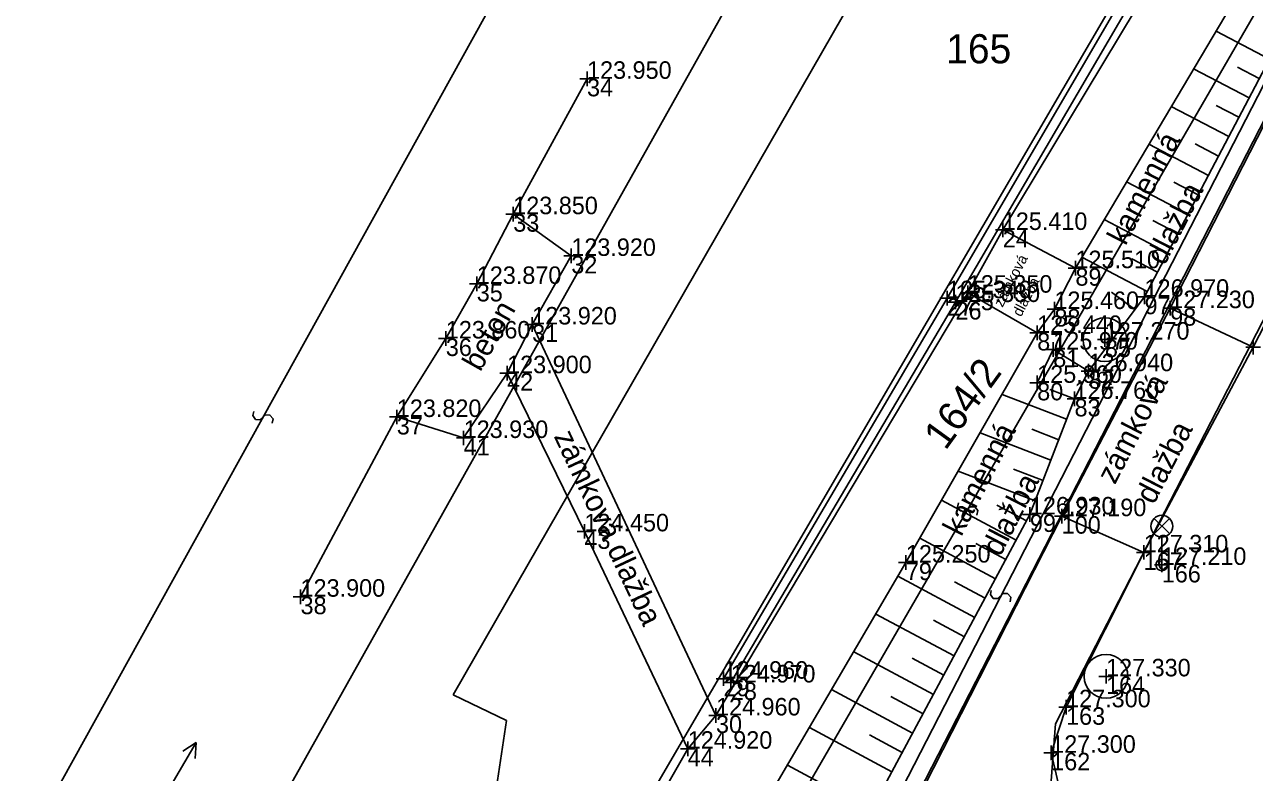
# Model space of a CAD drawing. Extents: x -747268 to -747054, y -964730 to -964532.
# Drawn here: x -747222.18 to -747180.02, y -964632.88 to -964607.25 of the extents above; entities that cross this region are included whole.
import ezdxf

# ---------------------------------------------------------------- set-up
doc = ezdxf.new("R2010")
doc.units = 0
for name, color, linetype in [('Body polohopisu', 7, 'Continuous'), ('Doplňkové značky', 7, 'Continuous'), ('KM', 7, 'Continuous'), ('Ploty_opěrné zdi', 7, 'Continuous'), ('Popisy objektů_povrchů', 7, 'Continuous'), ('Rozhraní ploch', 7, 'Continuous'), ('Vnitřní kresba', 7, 'Continuous'), ('Výškopis', 7, 'Continuous'), ('Výšky bodů', 7, 'Continuous'), ('Čísla bodů', 7, 'Continuous')]:
    doc.layers.add(name, color=color, linetype=linetype)

msp = doc.modelspace()

# ---------------------------------------------------------------- linework, layer by layer
at = {"layer": 'Body polohopisu'}
for p, q in [((-747202.9, -964609.11), (-747203.15, -964609.11)), ((-747202.9, -964609.11), (-747202.9, -964608.86)), ((-747202.9, -964609.11), (-747202.65, -964609.11)), ((-747202.9, -964609.11), (-747202.9, -964609.36)), ((-747205.43, -964613.75), (-747205.68, -964613.75)), ((-747205.43, -964613.75), (-747205.43, -964613.5)), ((-747205.43, -964613.75), (-747205.18, -964613.75)), ((-747205.43, -964613.75), (-747205.43, -964614)), ((-747188.65, -964614.29), (-747188.65, -964614.04)), ((-747188.65, -964614.29), (-747188.9, -964614.29)), ((-747188.65, -964614.29), (-747188.4, -964614.29)), ((-747188.65, -964614.29), (-747188.65, -964614.54)), ((-747203.44, -964615.18), (-747203.44, -964614.93)), ((-747203.44, -964615.18), (-747203.69, -964615.18)), ((-747203.44, -964615.18), (-747203.19, -964615.18)), ((-747203.44, -964615.18), (-747203.44, -964615.43)), ((-747186.16, -964615.6), (-747186.16, -964615.35)), ((-747206.68, -964616.14), (-747206.68, -964615.89)), ((-747186.16, -964615.6), (-747186.41, -964615.6)), ((-747186.16, -964615.6), (-747185.91, -964615.6)), ((-747186.16, -964615.6), (-747186.16, -964615.85)), ((-747206.68, -964616.14), (-747206.93, -964616.14)), ((-747206.68, -964616.14), (-747206.43, -964616.14)), ((-747206.68, -964616.14), (-747206.68, -964616.39)), ((-747189.85, -964616.44), (-747189.85, -964616.19)), ((-747190.56, -964616.63), (-747190.81, -964616.63)), ((-747190.56, -964616.63), (-747190.56, -964616.38)), ((-747190.56, -964616.63), (-747190.31, -964616.63)), ((-747190.56, -964616.63), (-747190.56, -964616.88)), ((-747190.27, -964616.76), (-747190.27, -964616.51)), ((-747189.85, -964616.44), (-747190.1, -964616.44)), ((-747189.85, -964616.44), (-747189.6, -964616.44)), ((-747189.85, -964616.44), (-747189.85, -964616.69)), ((-747183.79, -964616.58), (-747184.04, -964616.58)), ((-747183.79, -964616.58), (-747183.79, -964616.33)), ((-747183.79, -964616.58), (-747183.54, -964616.58)), ((-747183.79, -964616.58), (-747183.79, -964616.83)), ((-747182.91, -964616.97), (-747182.91, -964616.72)), ((-747190.27, -964616.76), (-747190.52, -964616.76)), ((-747190.27, -964616.76), (-747190.02, -964616.76)), ((-747190.27, -964616.76), (-747190.27, -964617.01)), ((-747186.88, -964617), (-747187.13, -964617)), ((-747186.88, -964617), (-747186.88, -964616.75)), ((-747186.88, -964617), (-747186.63, -964617)), ((-747186.88, -964617), (-747186.88, -964617.25)), ((-747182.91, -964616.97), (-747183.16, -964616.97)), ((-747182.91, -964616.97), (-747182.66, -964616.97)), ((-747182.91, -964616.97), (-747182.91, -964617.22)), ((-747204.78, -964617.53), (-747205.03, -964617.53)), ((-747204.78, -964617.53), (-747204.78, -964617.28)), ((-747204.78, -964617.53), (-747204.53, -964617.53)), ((-747204.78, -964617.53), (-747204.78, -964617.78)), ((-747187.47, -964617.82), (-747187.47, -964617.57)), ((-747207.74, -964618.01), (-747207.74, -964617.76)), ((-747187.47, -964617.82), (-747187.72, -964617.82)), ((-747187.47, -964617.82), (-747187.22, -964617.82)), ((-747187.47, -964617.82), (-747187.47, -964618.07)), ((-747185.15, -964618.05), (-747185.15, -964617.8)), ((-747207.74, -964618.01), (-747207.99, -964618.01)), ((-747207.74, -964618.01), (-747207.49, -964618.01)), ((-747207.74, -964618.01), (-747207.74, -964618.26)), ((-747186.92, -964618.39), (-747187.17, -964618.39)), ((-747186.92, -964618.39), (-747186.92, -964618.14)), ((-747186.92, -964618.39), (-747186.67, -964618.39)), ((-747186.92, -964618.39), (-747186.92, -964618.64)), ((-747185.15, -964618.05), (-747185.4, -964618.05)), ((-747185.15, -964618.05), (-747184.9, -964618.05)), ((-747185.15, -964618.05), (-747185.15, -964618.3)), ((-747180.07, -964618.31), (-747180.32, -964618.31)), ((-747180.07, -964618.31), (-747180.07, -964618.06)), ((-747180.07, -964618.31), (-747179.82, -964618.31)), ((-747180.07, -964618.31), (-747180.07, -964618.56)), ((-747205.64, -964619.2), (-747205.89, -964619.2)), ((-747205.64, -964619.2), (-747205.64, -964618.95)), ((-747205.64, -964619.2), (-747205.39, -964619.2)), ((-747205.64, -964619.2), (-747205.64, -964619.45)), ((-747185.71, -964619.13), (-747185.96, -964619.13)), ((-747185.71, -964619.13), (-747185.71, -964618.88)), ((-747185.71, -964619.13), (-747185.46, -964619.13)), ((-747185.71, -964619.13), (-747185.71, -964619.38)), ((-747187.47, -964619.53), (-747187.72, -964619.53)), ((-747187.47, -964619.53), (-747187.47, -964619.28)), ((-747187.47, -964619.53), (-747187.22, -964619.53)), ((-747187.47, -964619.53), (-747187.47, -964619.78)), ((-747186.19, -964620.08), (-747186.44, -964620.08)), ((-747186.19, -964620.08), (-747186.19, -964619.83)), ((-747186.19, -964620.08), (-747185.94, -964620.08)), ((-747186.19, -964620.08), (-747186.19, -964620.33)), ((-747209.42, -964620.7), (-747209.42, -964620.45)), ((-747209.42, -964620.7), (-747209.67, -964620.7)), ((-747209.42, -964620.7), (-747209.17, -964620.7)), ((-747209.42, -964620.7), (-747209.42, -964620.95)), ((-747207.13, -964621.42), (-747207.13, -964621.17)), ((-747207.13, -964621.42), (-747207.38, -964621.42)), ((-747207.13, -964621.42), (-747206.88, -964621.42)), ((-747207.13, -964621.42), (-747207.13, -964621.67)), ((-747187.72, -964624.04), (-747187.72, -964623.79)), ((-747186.63, -964624.1), (-747186.63, -964623.85)), ((-747187.72, -964624.04), (-747187.97, -964624.04)), ((-747187.72, -964624.04), (-747187.47, -964624.04)), ((-747187.72, -964624.04), (-747187.72, -964624.29)), ((-747186.63, -964624.1), (-747186.88, -964624.1)), ((-747186.63, -964624.1), (-747186.38, -964624.1)), ((-747186.63, -964624.1), (-747186.63, -964624.35)), ((-747202.99, -964624.62), (-747203.24, -964624.62)), ((-747202.99, -964624.62), (-747202.99, -964624.37)), ((-747202.99, -964624.62), (-747202.74, -964624.62)), ((-747202.99, -964624.62), (-747202.99, -964624.87)), ((-747183.82, -964625.34), (-747183.82, -964625.09)), ((-747191.97, -964625.69), (-747191.97, -964625.44)), ((-747183.82, -964625.34), (-747184.07, -964625.34)), ((-747183.82, -964625.34), (-747183.57, -964625.34)), ((-747183.82, -964625.34), (-747183.82, -964625.59)), ((-747183.2, -964625.77), (-747183.2, -964625.52)), ((-747191.97, -964625.69), (-747192.22, -964625.69)), ((-747191.97, -964625.69), (-747191.72, -964625.69)), ((-747191.97, -964625.69), (-747191.97, -964625.94)), ((-747183.2, -964625.77), (-747183.45, -964625.77)), ((-747183.2, -964625.77), (-747182.95, -964625.77)), ((-747183.2, -964625.77), (-747183.2, -964626.02)), ((-747212.72, -964626.86), (-747212.72, -964626.61)), ((-747212.72, -964626.86), (-747212.97, -964626.86)), ((-747212.72, -964626.86), (-747212.47, -964626.86)), ((-747212.72, -964626.86), (-747212.72, -964627.11)), ((-747185.11, -964629.59), (-747185.11, -964629.34)), ((-747198.22, -964629.67), (-747198.47, -964629.67)), ((-747198.22, -964629.67), (-747198.22, -964629.42)), ((-747198.22, -964629.67), (-747197.97, -964629.67)), ((-747198.22, -964629.67), (-747198.22, -964629.92)), ((-747197.97, -964629.8), (-747198.22, -964629.8)), ((-747197.97, -964629.8), (-747197.97, -964629.55)), ((-747197.97, -964629.8), (-747197.72, -964629.8)), ((-747197.97, -964629.8), (-747197.97, -964630.05)), ((-747185.11, -964629.59), (-747185.36, -964629.59)), ((-747185.11, -964629.59), (-747184.86, -964629.59)), ((-747185.11, -964629.59), (-747185.11, -964629.84)), ((-747186.48, -964630.65), (-747186.73, -964630.65)), ((-747186.48, -964630.65), (-747186.48, -964630.4)), ((-747186.48, -964630.65), (-747186.23, -964630.65)), ((-747186.48, -964630.65), (-747186.48, -964630.9)), ((-747198.48, -964630.93), (-747198.73, -964630.93)), ((-747198.48, -964630.93), (-747198.48, -964630.68)), ((-747198.48, -964630.93), (-747198.23, -964630.93)), ((-747198.48, -964630.93), (-747198.48, -964631.18)), ((-747199.45, -964632.07), (-747199.45, -964631.82)), ((-747199.45, -964632.07), (-747199.7, -964632.07)), ((-747199.45, -964632.07), (-747199.2, -964632.07)), ((-747199.45, -964632.07), (-747199.45, -964632.32)), ((-747186.99, -964632.21), (-747187.24, -964632.21)), ((-747186.99, -964632.21), (-747186.99, -964631.96)), ((-747186.99, -964632.21), (-747186.74, -964632.21)), ((-747186.99, -964632.21), (-747186.99, -964632.46))]:
    msp.add_line(p, q, dxfattribs=at)
at = {"layer": 'Doplňkové značky'}
for p, q in [((-747183.464, -964624.708), (-747182.936, -964624.18)), ((-747182.928, -964624.705), (-747183.456, -964624.176)), ((-747183.2, -964624.82), (-747183.2, -964625.57))]:
    msp.add_line(p, q, dxfattribs=at)
for centre, radius in [((-747185.15, -964618.05), 0.75), ((-747183.2, -964624.445), 0.375), ((-747183.2, -964625.77), 0.2), ((-747185.11, -964629.59), 0.75)]:
    msp.add_circle(centre, radius, dxfattribs=at)
at = {"layer": 'KM'}
for p, q in [((-747217.82, -964634.444), (-747216.296, -964631.86)), ((-747216.296, -964631.86), (-747216.76, -964632.153)), ((-747216.296, -964631.86), (-747216.329, -964632.408))]:
    msp.add_line(p, q, dxfattribs=at)
for points in [[(-747258.428, -964718.402), (-747225.89, -964656.18), (-747178.58, -964571.79), (-747161.768, -964542.826)], [(-747245.973, -964725.574), (-747237.39, -964710.13), (-747213.15, -964663.66), (-747212.04, -964661.58), (-747205.52, -964649.38), (-747207.93, -964646.01), (-747172.64, -964585.56), (-747171.18, -964583.16), (-747172.38, -964582.51), (-747172.75, -964582.31), (-747169.52, -964576.73), (-747168.08, -964577.53), (-747165.21, -964574.13), (-747160.86, -964564.14), (-747155.16, -964551.47), (-747155.48, -964551.37), (-747155.09, -964550.12), (-747154.28, -964550.33), (-747154.06, -964549.5), (-747153.365, -964547.044)], [(-747242.047, -964727.609), (-747230.16, -964705.36), (-747208.97, -964665.66), (-747208.88, -964665.32), (-747209.05, -964664.92), (-747208.39, -964663.57), (-747207.91, -964663.49), (-747207.6, -964663.09), (-747199.41, -964647.48), (-747199.14, -964646.95), (-747194.94, -964639.04), (-747194.8, -964638.66), (-747194.08, -964638.4), (-747193.89, -964638.17), (-747178.12, -964607.48), (-747165.52, -964582.92), (-747162.81, -964577.62), (-747161.38, -964574.2), (-747160.49, -964571.42), (-747153.77, -964550.39), (-747154.12, -964550.42), (-747153.81, -964549.44), (-747153.109, -964547.254)], [(-747149.729, -964549.086), (-747149.93, -964549.71), (-747150.35, -964549.8), (-747157.75, -964573.23), (-747158.53, -964575.6), (-747159.7, -964578.37), (-747163.23, -964585.33), (-747175.42, -964609.03), (-747186.84, -964631.22), (-747187.01, -964633.47), (-747185.08, -964635.94), (-747196.29, -964656.98), (-747198.54, -964658.68), (-747199.84, -964658.63), (-747201.84, -964659.38), (-747202.78, -964660.64), (-747203.73, -964662.42), (-747219.36, -964691.72)]]:
    msp.add_lwpolyline(points, dxfattribs=at)
at = {"layer": 'Ploty_opěrné zdi'}
for points in [[(-747169.11, -964579.94), (-747175.36, -964590.58), (-747182.97, -964603.61), (-747190.56, -964616.63), (-747198.22, -964629.67)], [(-747168.99, -964580.15), (-747175.05, -964590.69), (-747182.64, -964603.71), (-747190.27, -964616.76), (-747197.97, -964629.8)], [(-747187.47, -964619.53), (-747186.92, -964618.39), (-747185.71, -964619.13), (-747186.19, -964620.08)]]:
    msp.add_lwpolyline(points, dxfattribs=at)
at = {"layer": 'Rozhraní ploch'}
for points in [[(-747154.77, -964553.45), (-747158.98, -964567.07), (-747160.49, -964571.42), (-747165.45, -964575.44), (-747168.74, -964580.34), (-747174.87, -964590.85), (-747182.36, -964603.84), (-747188.65, -964614.29), (-747189.85, -964616.44), (-747198.48, -964630.93), (-747204.78, -964617.53), (-747203.44, -964615.18), (-747205.43, -964613.75), (-747206.68, -964616.14)], [(-747164.8, -964581.46), (-747168.98, -964589.75), (-747182.91, -964616.97), (-747186.63, -964624.1), (-747193.85, -964638.28), (-747194.38, -964638.56), (-747199.08, -964647.44), (-747204.82, -964658.33), (-747208.77, -964665.45), (-747214.7, -964676.73), (-747220.35, -964687.31), (-747228.95, -964703.36)], [(-747186.16, -964615.6), (-747180.42, -964605.92), (-747172.31, -964591.8), (-747166.51, -964582.26), (-747165.78, -964581.39), (-747164.8, -964581.46)], [(-747185.39, -964635.93), (-747186.36, -964634.9), (-747186.99, -964632.21), (-747186.48, -964630.65), (-747183.82, -964625.34), (-747180.07, -964618.31), (-747170.65, -964599.99), (-747161.67, -964582.51), (-747155.9, -964583.06)], [(-747188.65, -964614.29), (-747186.16, -964615.6)], [(-747186.88, -964617), (-747186.16, -964615.6)], [(-747206.68, -964616.14), (-747207.74, -964618.01)], [(-747187.47, -964617.82), (-747189.85, -964616.44)], [(-747211.81, -964661.77), (-747212.46, -964661), (-747212.25, -964659.9), (-747208, -964652.82), (-747198.3, -964636.51), (-747191.97, -964625.69), (-747187.47, -964617.82), (-747186.88, -964617)], [(-747180.07, -964618.31), (-747182.91, -964616.97)], [(-747205.64, -964619.2), (-747204.78, -964617.53)], [(-747207.74, -964618.01), (-747209.42, -964620.7), (-747207.13, -964621.42), (-747205.64, -964619.2), (-747202.99, -964624.62), (-747199.45, -964632.07), (-747215.93, -964660.89), (-747224.57, -964675.08), (-747231.76, -964687.56), (-747236.28, -964694.89), (-747237.94, -964696.27), (-747242.26, -964695.59), (-747246.85, -964693), (-747247.82, -964691.84), (-747248.23, -964692.9)], [(-747186.63, -964624.1), (-747183.82, -964625.34)], [(-747199.45, -964632.07), (-747198.48, -964630.93)]]:
    msp.add_lwpolyline(points, dxfattribs=at)
at = {"layer": 'Vnitřní kresba'}
for p, q in [((-747231.87, -964652.97), (-747184.5, -964567.43)), ((-747179.63, -964581.7), (-747207.49, -964630.22)), ((-747199.15, -964639.91), (-747166.09, -964582.82)), ((-747166.09, -964582.82), (-747194.8, -964638.66)), ((-747207.49, -964630.22), (-747205.66, -964631.1)), ((-747205.66, -964631.1), (-747207.93, -964646.01))]:
    msp.add_line(p, q, dxfattribs=at)
for points in [[(-747213.69, -964620.916), (-747213.661, -964620.76), (-747213.768, -964620.633), (-747213.92, -964620.628), (-747214.11, -964620.797), (-747214.262, -964620.782), (-747214.355, -964620.65), (-747214.322, -964620.508)], [(-747189.541, -964624.066), (-747189.509, -964623.911), (-747189.613, -964623.781), (-747189.765, -964623.774), (-747189.959, -964623.939), (-747190.11, -964623.921), (-747190.201, -964623.788), (-747190.165, -964623.646)], [(-747188.4, -964627.032), (-747188.376, -964626.875), (-747188.486, -964626.751), (-747188.638, -964626.752), (-747188.824, -964626.926), (-747188.976, -964626.916), (-747189.073, -964626.787), (-747189.044, -964626.644)]]:
    msp.add_lwpolyline(points, dxfattribs=at)
at = {"layer": 'Výškopis'}
for points in [[(-747164.8, -964581.46), (-747168.98, -964589.75), (-747173.09, -964596.22), (-747183.79, -964616.58), (-747185.71, -964619.13)], [(-747179.51, -964608.436), (-747181.341, -964607.474)], [(-747179.859, -964609.1), (-747180.605, -964608.708)], [(-747205.43, -964613.75), (-747202.9, -964609.11)], [(-747180.208, -964609.764), (-747182.108, -964608.766)], [(-747180.906, -964611.092), (-747182.874, -964610.058)], [(-747180.557, -964610.428), (-747181.33, -964610.022)], [(-747181.604, -964612.42), (-747183.64, -964611.35)], [(-747181.255, -964611.756), (-747182.056, -964611.335)], [(-747182.301, -964613.748), (-747184.406, -964612.642)], [(-747181.953, -964613.084), (-747182.781, -964612.649)], [(-747182.999, -964615.075), (-747185.172, -964613.934)], [(-747182.65, -964614.412), (-747183.506, -964613.962)], [(-747183.697, -964616.403), (-747185.938, -964615.226)], [(-747183.348, -964615.739), (-747184.231, -964615.275)], [(-747184.121, -964617.02), (-747184.918, -964616.42)], [(-747211.81, -964661.77), (-747207.07, -964653.04), (-747198.3, -964636.51), (-747191.97, -964625.69), (-747187.47, -964617.82)], [(-747186.19, -964620.08), (-747187.72, -964624.04), (-747195.58, -964638.7)], [(-747186.46, -964620.78), (-747188.673, -964619.925)], [(-747186.19, -964620.08), (-747187.033, -964619.754)], [(-747209.42, -964620.7), (-747212.72, -964626.86)], [(-747187.001, -964622.179), (-747189.426, -964621.242)], [(-747186.731, -964621.479), (-747187.658, -964621.121)], [(-747187.541, -964623.578), (-747190.18, -964622.559)], [(-747187.271, -964622.878), (-747188.284, -964622.487)], [(-747188.195, -964624.925), (-747190.75, -964623.556)], [(-747187.84, -964624.264), (-747188.855, -964623.72)], [(-747188.904, -964626.247), (-747191.494, -964624.858)], [(-747188.549, -964625.586), (-747189.578, -964625.035)], [(-747189.612, -964627.569), (-747192.244, -964626.158)], [(-747189.258, -964626.908), (-747190.302, -964626.349)], [(-747190.321, -964628.891), (-747193.002, -964627.454)], [(-747189.967, -964628.23), (-747191.029, -964627.661)], [(-747191.03, -964630.213), (-747193.76, -964628.75)], [(-747190.675, -964629.552), (-747191.758, -964628.972)], [(-747191.739, -964631.535), (-747194.518, -964630.045)], [(-747191.384, -964630.874), (-747192.486, -964630.284)], [(-747192.447, -964632.857), (-747195.276, -964631.341)], [(-747192.093, -964632.196), (-747193.215, -964631.595)], [(-747193.156, -964634.179), (-747196.034, -964632.636)]]:
    msp.add_lwpolyline(points, dxfattribs=at)

# ---------------------------------------------------------------- texts
at = {"layer": 'KM'}
msp.add_text('165', height=1, dxfattribs=at).set_placement((-747190.59, -964608.58))
msp.add_text('164/2', height=1, rotation=54, dxfattribs=at).set_placement((-747190.616, -964621.876))
at = {"layer": 'Popisy objektů_povrchů'}
for s, height, rotation, p in [('kamenná', 0.75, 62.7676, (-747184.441, -964614.856)), ('dlažba', 0.75, 62.7676, (-747183.108, -964615.542)), ('zámková', 0.3587, 62.7676, (-747188.66, -964616.96)), ('dlažba', 0.3587, 62.7676, (-747188.022, -964617.289)), ('beton', 0.75, 60.4535, (-747206.56, -964619.178)), ('zámková', 0.75, 62.7676, (-747184.807, -964623.043)), ('kamenná', 0.75, 62.7676, (-747190.074, -964624.827)), ('dlažba', 0.75, 62.7676, (-747183.473, -964623.73)), ('zámková dlažba', 0.75, 295.1805, (-747204.048, -964621.36)), ('dlažba', 0.75, 62.7676, (-747188.74, -964625.514))]:
    msp.add_text(s, height=height, rotation=rotation, dxfattribs=at).set_placement(p)
at = {"layer": 'Výšky bodů'}
for s, p in [('123.950', (-747202.9, -964609.11)), ('123.850', (-747205.43, -964613.75)), ('125.410', (-747188.65, -964614.29)), ('123.920', (-747203.44, -964615.18)), ('125.510', (-747186.16, -964615.6)), ('123.870', (-747206.68, -964616.14)), ('125.350', (-747189.85, -964616.44)), ('125.340', (-747190.56, -964616.63)), ('125.330', (-747190.27, -964616.76)), ('126.970', (-747183.79, -964616.58)), ('125.460', (-747186.88, -964617)), ('127.230', (-747182.91, -964616.97)), ('123.920', (-747204.78, -964617.53)), ('123.860', (-747207.74, -964618.01)), ('125.440', (-747187.47, -964617.82)), ('127.270', (-747185.15, -964618.05)), ('125.970', (-747186.92, -964618.39)), ('123.900', (-747205.64, -964619.2)), ('126.940', (-747185.71, -964619.13)), ('125.960', (-747187.47, -964619.53)), ('126.760', (-747186.19, -964620.08)), ('123.820', (-747209.42, -964620.7)), ('123.930', (-747207.13, -964621.42)), ('126.930', (-747187.72, -964624.04)), ('127.190', (-747186.63, -964624.1)), ('124.450', (-747202.99, -964624.62)), ('127.310', (-747183.82, -964625.34)), ('125.250', (-747191.97, -964625.69)), ('127.210', (-747183.2, -964625.77)), ('123.900', (-747212.72, -964626.86)), ('124.960', (-747198.22, -964629.67)), ('124.970', (-747197.97, -964629.8)), ('127.330', (-747185.11, -964629.59)), ('127.300', (-747186.48, -964630.65)), ('124.960', (-747198.48, -964630.93)), ('124.920', (-747199.45, -964632.07)), ('127.300', (-747186.99, -964632.21))]:
    msp.add_text(s, height=0.6, dxfattribs=at).set_placement(p)
at = {"layer": 'Čísla bodů'}
for s, p in [('34', (-747202.9, -964609.71)), ('33', (-747205.43, -964614.35)), ('24', (-747188.65, -964614.89)), ('32', (-747203.44, -964615.78)), ('89', (-747186.16, -964616.2)), ('35', (-747206.68, -964616.74)), ('27', (-747190.56, -964617.23)), ('25', (-747189.85, -964617.04)), ('97', (-747183.79, -964617.18)), ('26', (-747190.27, -964617.36)), ('88', (-747186.88, -964617.6)), ('98', (-747182.91, -964617.57)), ('31', (-747204.78, -964618.13)), ('36', (-747207.74, -964618.61)), ('87', (-747187.47, -964618.42)), ('81', (-747186.92, -964618.99)), ('85', (-747185.15, -964618.65)), ('42', (-747205.64, -964619.8)), ('82', (-747185.71, -964619.73)), ('80', (-747187.47, -964620.13)), ('83', (-747186.19, -964620.68)), ('37', (-747209.42, -964621.3)), ('41', (-747207.13, -964622.02)), ('99', (-747187.72, -964624.64)), ('100', (-747186.63, -964624.7)), ('43', (-747202.99, -964625.22)), ('167', (-747183.82, -964625.94)), ('79', (-747191.97, -964626.29)), ('166', (-747183.2, -964626.37)), ('38', (-747212.72, -964627.46)), ('29', (-747198.22, -964630.27)), ('28', (-747197.97, -964630.4)), ('164', (-747185.11, -964630.19)), ('163', (-747186.48, -964631.25)), ('30', (-747198.48, -964631.53)), ('44', (-747199.45, -964632.67)), ('162', (-747186.99, -964632.81))]:
    msp.add_text(s, height=0.6, dxfattribs=at).set_placement(p)

doc.saveas('drawing.dxf')
